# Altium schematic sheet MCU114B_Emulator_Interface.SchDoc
size 431 x 279 mm; Date: Not shown in title block; ApprovedBy: Not shown in title block; CheckedBy: Not shown in title block; Author: Not shown in title block; CompanyName: Not shown in title block; Engineer: Not shown in title block; Organization: Not shown in title block; Address1: Not shown in title block; Address2: Not shown in title block; Address3: Not shown in title block; Address4: Not shown in title block; DocumentNumber: 10; Revision: Use project parameter SCH_Rev; SheetNumber: 10; SheetTotal: 11; PageSetup: Record=PageOptions¦CenterHorizontal=True¦CenterVertical=True¦PrintScale=1.00¦XCorrection=1.00¦YCorrection=1.00¦PrintKind=0¦BorderSize=5000000¦LeftOffset=0¦BottomOffset=0¦Orientation=2¦PaperLength=1000¦PaperWidth=1000¦Scale=100¦PaperSource=15¦PrintQuality=600¦MediaType=1¦DitherType=10¦PaperKind=Letter¦PrintScaleMode=1
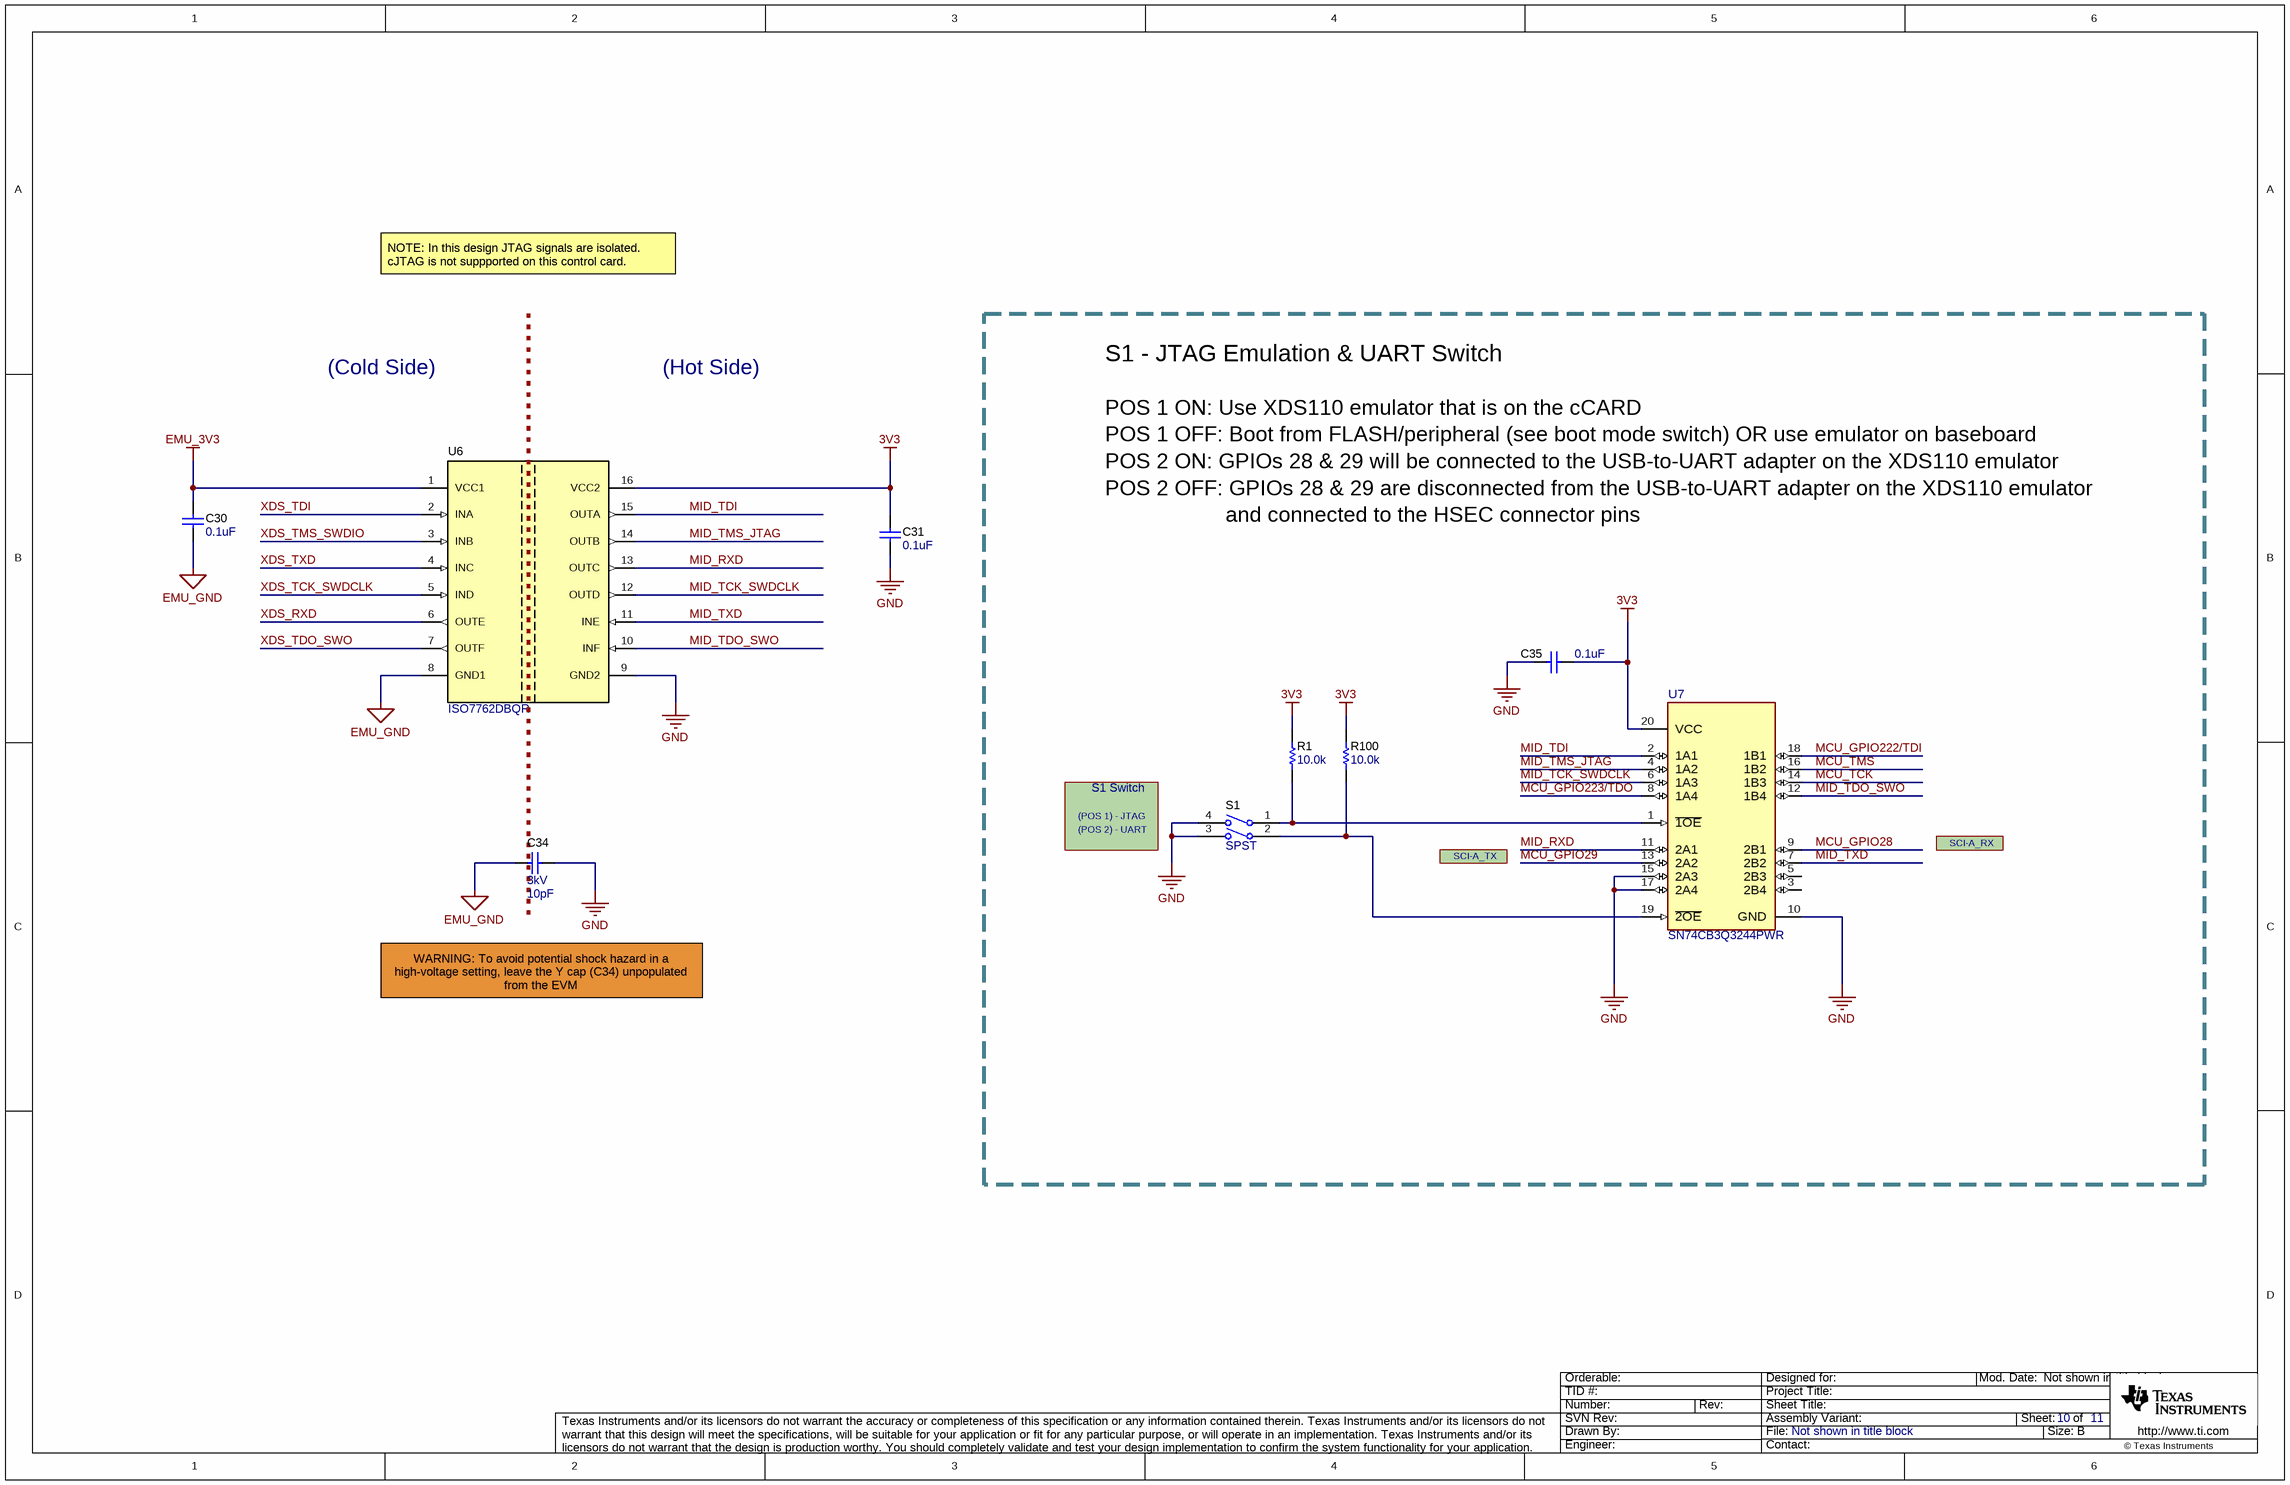
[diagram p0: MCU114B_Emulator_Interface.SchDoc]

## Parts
C30  ValueDisplayed: 0.1uF  [0402]  (hidden comment: 885012205037)
C31  ValueDisplayed: 0.1uF  [0402]  (hidden comment: 885012205037)
C34  VDC_V: 3kV  ValueDisplayed: 10pF  [1812_180]  (hidden comment: C1812C100JHGACTU)
C35  ValueDisplayed: 0.1uF  [0402]  (hidden comment: 885012205037)
R1  ValueDisplayed: 10.0k  [0402]  (hidden comment: AC0402FR-0710KL)
R100  ValueDisplayed: 10.0k  [0402]  (hidden comment: AC0402FR-0710KL)
S1  Circuit: SPST  [SW_218-2LP]  (hidden comment: 218-2LPST)
U6  ISO7762DBQR  [DBQ0016A_N]
U7  SN74CB3Q3244PWR  [PW0020A-MFG]

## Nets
3V3: C31.1 C35.1 R1.2 R100.2 U6.16(VCC2) U7.20(VCC)
EMU_3V3: C30.1 U6.1(VCC1)
EMU_GND: C30.2 C34.2 U6.8(GND1)
GND: C31.2 C34.1 C35.2 S1.3 S1.4 U6.9(GND2) U7.10(GND) U7.15(2A3) U7.17(2A4)
MCU_GPIO28: U7.9(2B1)
MCU_GPIO29: U7.13(2A2)
MCU_GPIO222/TDI: U7.18(1B1)
MCU_GPIO223/TDO: U7.8(1A4)
MCU_TCK: U7.14(1B3)
MCU_TMS: U7.16(1B2)
MID_RXD: U6.13(OUTC) U7.11(2A1)
MID_TCK_SWDCLK: U6.12(OUTD) U7.6(1A3)
MID_TDI: U6.15(OUTA) U7.2(1A1)
MID_TDO_SWO: U6.10(INF) U7.12(1B4)
MID_TMS_JTAG: U6.14(OUTB) U7.4(1A2)
MID_TXD: U6.11(INE) U7.7(2B2)
XDS_RXD: U6.6(OUTE)
XDS_TCK_SWDCLK: U6.5(IND)
XDS_TDI: U6.2(INA)
XDS_TDO_SWO: U6.7(OUTF)
XDS_TMS_SWDIO: U6.3(INB)
XDS_TXD: U6.4(INC)
NetR1_1: R1.1 S1.1 U7.1(~{1OE})
NetR100_1: R100.1 S1.2 U7.19(~{2OE})

Not connected (* = marked no-connect by the designer): U7 3(2B4) 5(2B3)

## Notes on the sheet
- NOTE: In this design JTAG signals are isolated. cJTAG is not suppported on this control card.
- S1 - JTAG Emulation & UART Switch
- (Cold Side)
- (Hot Side)
- POS 1 ON: Use XDS110 emulator that is on the cCARD
- POS 1 OFF: Boot from FLASH/peripheral (see boot mode switch) OR use emulator on baseboard
- POS 2 ON: GPIOs 28 & 29 will be connected to the USB-to-UART adapter on the XDS110 emulator
- POS 2 OFF: GPIOs 28 & 29 are disconnected from the USB-to-UART adapter on the XDS110 emulator
- and connected to the HSEC connector pins
- (POS 1) - JTAG
- (POS 2) - UART
- S1 Switch
- SCI-A_TX
- SCI-A_RX
- WARNING: To avoid potential shock hazard in a high-voltage setting, leave the Y cap (C34) unpopulated from the EVM

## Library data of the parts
C30 C31 C35 = CMP-0006228-2: CAP, CERM, 0.1 uF, 16 V, +/- 10%, X7R, 0402; Manufacturer: Wurth Elektronik; TaMin_C: -55°C; Polarized: N; SizeAreaWB_mm2: 3; Value1: Unknown; U/M: EA; Value: 0.1uF; TaMax_C: 125°C; SizeZ_mm: 0.6; SizeX_mm: 1; SizeY_mm: 0.5; Value2: 16V; Cap_F: 100nF; AEC Category: Q200
C34 = CMP-0082066-1: CAP, CERM, 10 pF, 3000 V,+/- 5%, C0G/NP0, AEC-Q200 Grade 1, 1812; Manufacturer: Kemet; SizeAreaWB_mm2: 23.1; SizeArea_mm2: 14.4; AEC Qualified: Y; AEC Category: Q200; Value: 10pF; TaMax_C: 125°C; SizeZ_mm: 1.8; AEC Grade: 1; Polarized: N; TaMin_C: -55°C; SizeY_mm: 3.2; Value2: 3000V; U/M: EA; SizeX_mm: 4.5; Cap_Case: 1812
R1 R100 = CMP-0077731-1: RES, 10.0 k, 1%, 0.063 W, AEC-Q200 Grade 0, 0402; Manufacturer: Yageo America; Power_W: 63mW; TempCo: 100 ppm/C; Value_Code: 10k0; U/M: EA; Value: 10.0k; EIA_Code: E96; Res_ohm: 10k; SizeX_mm: 1.0; SizeY_mm: 0.5; SizeZ_mm: 0.6; Value2: 0.063W; AEC Qualified: Y; VDC_V: 50V; AEC Grade: 0; AEC Category: Q200
S1 = CMP-0002230-1: Switch, SPST, 2 Pos, 25mA, 24VDC, SMD; Manufacturer: CTS Electrocomponents; VDC_V: 24V; SwitchFunction: Off-On; PositionCount: 2; CurrentRating_mA: 25A
U6 = CMP-0067607-3: High Speed, Robust EMC, Reinforced Six-Channel Digital Isolator, DBQ0016A (SSOP-16); Manufacturer: Texas Instruments; SizeX_mm: 6.0; SizeY_mm: 10.0; CompType: IC; SizeZ_mm: 1.75; SizeArea_mm2: 60.0; SizeAreaWB_mm2: 96.0; U/M: EA; AEC Category: Q200; AEC Qualified: N
U7 = CMP-0091594-1: IC SW BUS 8B FET LV 20-TSSOP,3.3-V, 1:1 (SPST), 8-channel FET high bandwidth bus switch with 2 control inputs; Manufacturer: Texas Instruments; TaMax_C: +85°C; Propagation Delay: 0.2ns; AEC Qualified: No; TaMin_C: -40°C; Nominal Supply Current: 0.7mA; Number Of Outputs: 4; Min Supply Voltage: 2.3V; PositionCount: 2; SizeZ_mm: 1.2mm; Standoff Height: 0.05mm; Max Supply Voltage: 3.6V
